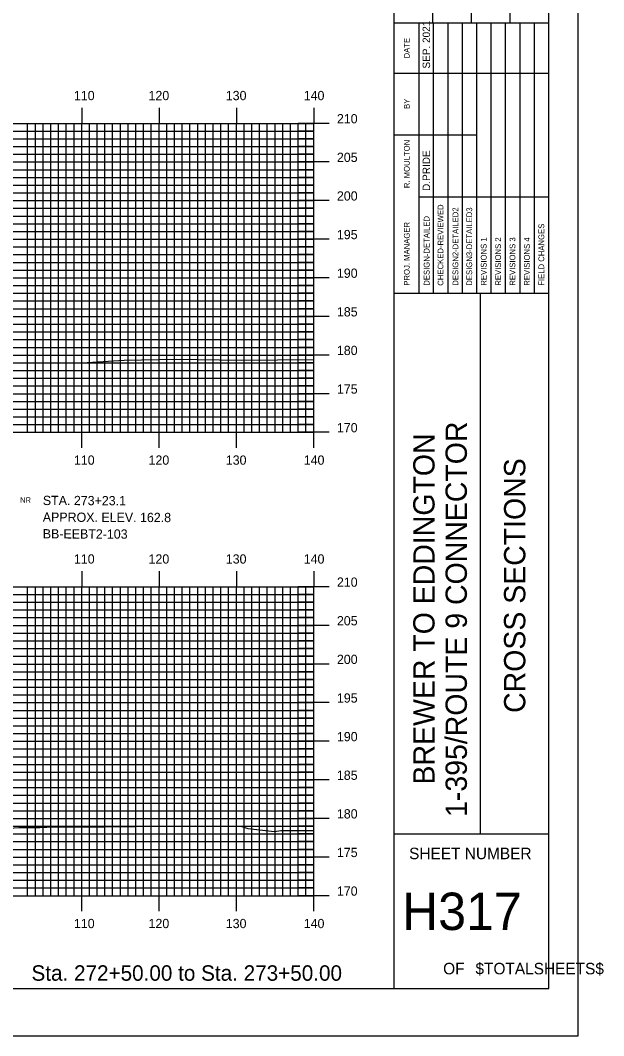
# Model space of a CAD drawing. Extents: x 1809013 to 1809356, y 442591 to 442811.
# Drawn here: x 1809280.4 to 1809355.8, y 442590.5 to 442722 of the extents above; entities that cross this region are included whole.
import ezdxf

# ---------------------------------------------------------------- set-up
doc = ezdxf.new("R2010")
doc.units = 0
for name, color, linetype in [('BORDER', 7, 'Continuous'), ('BORING - NO REFUSAL', 7, 'Continuous'), ('H_V ANNOTATION', 7, 'Continuous'), ('MAJOR', 7, 'Continuous'), ('MINOR', 7, 'Continuous'), ('PLOT BOUNDARY', 7, 'Continuous'), ('S_Roadway_Centerline', 7, 'Continuous')]:
    doc.layers.add(name, color=color, linetype=linetype)

msp = doc.modelspace()

# ---------------------------------------------------------------- linework, layer by layer
at = {"layer": 'BORDER'}
for p, q in [((1809328.72, 442596.67), (1809328.72, 442806.67)), ((1809333.72, 442721.67), (1809333.72, 442738.97)), ((1809338.72, 442721.67), (1809338.72, 442738.97)), ((1809343.72, 442721.67), (1809343.72, 442738.97)), ((1809328.72, 442721.67), (1809348.72, 442721.67)), ((1809328.72, 442686.67), (1809348.72, 442686.67)), ((1809339.91, 442616.67), (1809339.91, 442686.67)), ((1809328.72, 442616.67), (1809348.72, 442616.67))]:
    msp.add_line(p, q, dxfattribs=at)
msp.add_lwpolyline([(1809028.72, 442596.67), (1809348.72, 442596.67), (1809348.72, 442806.67), (1809028.72, 442806.67)], close=True, dxfattribs=at)
for points in [[(1809331.95, 442715.17), (1809331.95, 442721.67)], [(1809333.82, 442686.68), (1809333.82, 442721.67)], [(1809335.68, 442721.67), (1809335.68, 442686.68)], [(1809337.55, 442686.68), (1809337.55, 442721.67)], [(1809339.41, 442686.68), (1809339.41, 442721.67)], [(1809341.27, 442686.68), (1809341.27, 442721.67)], [(1809343.14, 442686.68), (1809343.14, 442721.67)], [(1809345, 442686.68), (1809345, 442721.67)], [(1809346.86, 442686.68), (1809346.86, 442721.67)], [(1809331.96, 442686.68), (1809331.96, 442720.26)], [(1809328.72, 442715.17), (1809348.72, 442715.17)], [(1809328.72, 442707.17), (1809331.96, 442707.17)], [(1809331.95, 442707.17), (1809339.41, 442707.17)], [(1809331.95, 442699.17), (1809348.72, 442699.17)]]:
    msp.add_lwpolyline(points, dxfattribs=at)
at = {"layer": 'MAJOR'}
for p, q in [((1809288.32, 442710.67), (1809288.32, 442708.67)), ((1809298.32, 442710.67), (1809298.32, 442708.67)), ((1809308.32, 442710.67), (1809308.32, 442708.67)), ((1809318.32, 442710.67), (1809318.32, 442708.67)), ((1809038.32, 442708.67), (1809318.32, 442708.67)), ((1809038.32, 442708.67), (1809318.32, 442708.67)), ((1809288.32, 442668.67), (1809288.32, 442708.67)), ((1809298.32, 442668.67), (1809298.32, 442708.67)), ((1809308.32, 442668.67), (1809308.32, 442708.67)), ((1809320.33, 442708.67), (1809316.32, 442708.67)), ((1809318.32, 442668.67), (1809318.32, 442708.67)), ((1809318.32, 442668.67), (1809318.32, 442708.67)), ((1809038.32, 442703.67), (1809318.32, 442703.67)), ((1809320.33, 442703.67), (1809316.32, 442703.67)), ((1809038.32, 442698.67), (1809318.32, 442698.67)), ((1809320.33, 442698.67), (1809316.32, 442698.67)), ((1809038.32, 442693.67), (1809318.32, 442693.67)), ((1809320.33, 442693.67), (1809316.32, 442693.67)), ((1809038.32, 442688.67), (1809318.32, 442688.67)), ((1809320.33, 442688.67), (1809316.32, 442688.67)), ((1809038.32, 442683.67), (1809318.32, 442683.67)), ((1809320.33, 442683.67), (1809316.32, 442683.67)), ((1809038.32, 442678.67), (1809318.32, 442678.67)), ((1809320.33, 442678.67), (1809316.32, 442678.67)), ((1809038.32, 442673.67), (1809318.32, 442673.67)), ((1809320.33, 442673.67), (1809316.32, 442673.67)), ((1809038.32, 442668.67), (1809318.32, 442668.67)), ((1809038.32, 442668.67), (1809318.32, 442668.67)), ((1809288.32, 442666.66), (1809288.32, 442668.67)), ((1809298.32, 442666.66), (1809298.32, 442668.67)), ((1809308.32, 442666.66), (1809308.32, 442668.67)), ((1809320.33, 442668.67), (1809316.32, 442668.67)), ((1809318.32, 442666.66), (1809318.32, 442668.67)), ((1809288.32, 442650.67), (1809288.32, 442648.67)), ((1809298.32, 442650.67), (1809298.32, 442648.67)), ((1809308.32, 442650.67), (1809308.32, 442648.67)), ((1809318.32, 442650.67), (1809318.32, 442648.67)), ((1809038.32, 442648.67), (1809318.32, 442648.67)), ((1809038.32, 442648.67), (1809318.32, 442648.67)), ((1809288.32, 442608.67), (1809288.32, 442648.67)), ((1809298.32, 442608.67), (1809298.32, 442648.67)), ((1809308.32, 442608.67), (1809308.32, 442648.67)), ((1809320.33, 442648.67), (1809316.32, 442648.67)), ((1809318.32, 442608.67), (1809318.32, 442648.67)), ((1809318.32, 442608.67), (1809318.32, 442648.67)), ((1809038.32, 442643.67), (1809318.32, 442643.67)), ((1809320.33, 442643.67), (1809316.32, 442643.67)), ((1809038.32, 442638.67), (1809318.32, 442638.67)), ((1809320.33, 442638.67), (1809316.32, 442638.67)), ((1809038.32, 442633.67), (1809318.32, 442633.67)), ((1809320.33, 442633.67), (1809316.32, 442633.67)), ((1809038.32, 442628.67), (1809318.32, 442628.67)), ((1809320.33, 442628.67), (1809316.32, 442628.67)), ((1809038.32, 442623.67), (1809318.32, 442623.67)), ((1809320.33, 442623.67), (1809316.32, 442623.67)), ((1809038.32, 442618.67), (1809318.32, 442618.67)), ((1809320.33, 442618.67), (1809316.32, 442618.67)), ((1809038.32, 442613.67), (1809318.32, 442613.67)), ((1809320.33, 442613.67), (1809316.32, 442613.67)), ((1809038.32, 442608.67), (1809318.32, 442608.67)), ((1809038.32, 442608.67), (1809318.32, 442608.67)), ((1809288.32, 442606.66), (1809288.32, 442608.67)), ((1809298.32, 442606.66), (1809298.32, 442608.67)), ((1809308.32, 442606.66), (1809308.32, 442608.67)), ((1809320.33, 442608.67), (1809316.32, 442608.67)), ((1809318.32, 442606.66), (1809318.32, 442608.67))]:
    msp.add_line(p, q, dxfattribs=at)
at = {"layer": 'MINOR'}
for p, q in [((1809281.32, 442668.67), (1809281.32, 442708.67)), ((1809282.32, 442668.67), (1809282.32, 442708.67)), ((1809283.32, 442668.67), (1809283.32, 442708.67)), ((1809284.32, 442668.67), (1809284.32, 442708.67)), ((1809285.32, 442668.67), (1809285.32, 442708.67)), ((1809286.32, 442668.67), (1809286.32, 442708.67)), ((1809287.32, 442668.67), (1809287.32, 442708.67)), ((1809289.32, 442668.67), (1809289.32, 442708.67)), ((1809290.32, 442668.67), (1809290.32, 442708.67)), ((1809291.32, 442668.67), (1809291.32, 442708.67)), ((1809292.32, 442668.67), (1809292.32, 442708.67)), ((1809293.32, 442668.67), (1809293.32, 442708.67)), ((1809294.32, 442668.67), (1809294.32, 442708.67)), ((1809295.32, 442668.67), (1809295.32, 442708.67)), ((1809296.32, 442668.67), (1809296.32, 442708.67)), ((1809297.32, 442668.67), (1809297.32, 442708.67)), ((1809299.32, 442668.67), (1809299.32, 442708.67)), ((1809300.32, 442668.67), (1809300.32, 442708.67)), ((1809301.32, 442668.67), (1809301.32, 442708.67)), ((1809302.32, 442668.67), (1809302.32, 442708.67)), ((1809303.32, 442668.67), (1809303.32, 442708.67)), ((1809304.32, 442668.67), (1809304.32, 442708.67)), ((1809305.32, 442668.67), (1809305.32, 442708.67)), ((1809306.32, 442668.67), (1809306.32, 442708.67)), ((1809307.32, 442668.67), (1809307.32, 442708.67)), ((1809309.32, 442668.67), (1809309.32, 442708.67)), ((1809310.32, 442668.67), (1809310.32, 442708.67)), ((1809311.32, 442668.67), (1809311.32, 442708.67)), ((1809312.32, 442668.67), (1809312.32, 442708.67)), ((1809313.32, 442668.67), (1809313.32, 442708.67)), ((1809314.32, 442668.67), (1809314.32, 442708.67)), ((1809315.32, 442668.67), (1809315.32, 442708.67)), ((1809316.32, 442668.67), (1809316.32, 442708.67)), ((1809317.32, 442668.67), (1809317.32, 442708.67)), ((1809038.32, 442707.67), (1809318.32, 442707.67)), ((1809318.32, 442707.67), (1809316.32, 442707.67)), ((1809038.32, 442706.67), (1809318.32, 442706.67)), ((1809038.32, 442705.67), (1809318.32, 442705.67)), ((1809318.32, 442706.67), (1809316.32, 442706.67)), ((1809318.32, 442705.67), (1809316.32, 442705.67)), ((1809038.32, 442704.67), (1809318.32, 442704.67)), ((1809318.32, 442704.67), (1809316.32, 442704.67)), ((1809038.32, 442702.67), (1809318.32, 442702.67)), ((1809038.32, 442701.67), (1809318.32, 442701.67)), ((1809318.32, 442702.67), (1809316.32, 442702.67)), ((1809318.32, 442701.67), (1809316.32, 442701.67)), ((1809038.32, 442700.67), (1809318.32, 442700.67)), ((1809318.32, 442700.67), (1809316.32, 442700.67)), ((1809038.32, 442699.67), (1809318.32, 442699.67)), ((1809318.32, 442699.67), (1809316.32, 442699.67)), ((1809038.32, 442697.67), (1809318.32, 442697.67)), ((1809318.32, 442697.67), (1809316.32, 442697.67)), ((1809038.32, 442696.67), (1809318.32, 442696.67)), ((1809318.32, 442696.67), (1809316.32, 442696.67)), ((1809038.32, 442695.67), (1809318.32, 442695.67)), ((1809318.32, 442695.67), (1809316.32, 442695.67)), ((1809038.32, 442694.67), (1809318.32, 442694.67)), ((1809318.32, 442694.67), (1809316.32, 442694.67)), ((1809038.32, 442692.67), (1809318.32, 442692.67)), ((1809318.32, 442692.67), (1809316.32, 442692.67)), ((1809038.32, 442691.67), (1809318.32, 442691.67)), ((1809318.32, 442691.67), (1809316.32, 442691.67)), ((1809038.32, 442690.67), (1809318.32, 442690.67)), ((1809318.32, 442690.67), (1809316.32, 442690.67)), ((1809038.32, 442689.67), (1809318.32, 442689.67)), ((1809318.32, 442689.67), (1809316.32, 442689.67)), ((1809038.32, 442687.67), (1809318.32, 442687.67)), ((1809318.32, 442687.67), (1809316.32, 442687.67)), ((1809038.32, 442686.67), (1809318.32, 442686.67)), ((1809318.32, 442686.67), (1809316.32, 442686.67)), ((1809038.32, 442685.67), (1809318.32, 442685.67)), ((1809038.32, 442684.67), (1809318.32, 442684.67)), ((1809318.32, 442685.67), (1809316.32, 442685.67)), ((1809318.32, 442684.67), (1809316.32, 442684.67)), ((1809038.32, 442682.67), (1809318.32, 442682.67)), ((1809318.32, 442682.67), (1809316.32, 442682.67)), ((1809038.32, 442681.67), (1809318.32, 442681.67)), ((1809038.32, 442680.67), (1809318.32, 442680.67)), ((1809318.32, 442681.67), (1809316.32, 442681.67)), ((1809318.32, 442680.67), (1809316.32, 442680.67)), ((1809038.32, 442679.67), (1809318.32, 442679.67)), ((1809318.32, 442679.67), (1809316.32, 442679.67)), ((1809038.32, 442677.67), (1809318.32, 442677.67)), ((1809038.32, 442676.67), (1809318.32, 442676.67)), ((1809318.32, 442677.67), (1809316.32, 442677.67)), ((1809318.32, 442676.67), (1809316.32, 442676.67)), ((1809038.32, 442675.67), (1809318.32, 442675.67)), ((1809318.32, 442675.67), (1809316.32, 442675.67)), ((1809038.32, 442674.67), (1809318.32, 442674.67)), ((1809318.32, 442674.67), (1809316.32, 442674.67)), ((1809038.32, 442672.67), (1809318.32, 442672.67)), ((1809318.32, 442672.67), (1809316.32, 442672.67)), ((1809038.32, 442671.67), (1809318.32, 442671.67)), ((1809318.32, 442671.67), (1809316.32, 442671.67)), ((1809038.32, 442670.67), (1809318.32, 442670.67)), ((1809318.32, 442670.67), (1809316.32, 442670.67)), ((1809038.32, 442669.67), (1809318.32, 442669.67)), ((1809318.32, 442669.67), (1809316.32, 442669.67)), ((1809038.32, 442647.67), (1809318.32, 442647.67)), ((1809281.32, 442608.67), (1809281.32, 442648.67)), ((1809282.32, 442608.67), (1809282.32, 442648.67)), ((1809283.32, 442608.67), (1809283.32, 442648.67)), ((1809284.32, 442608.67), (1809284.32, 442648.67)), ((1809285.32, 442608.67), (1809285.32, 442648.67)), ((1809286.32, 442608.67), (1809286.32, 442648.67)), ((1809287.32, 442608.67), (1809287.32, 442648.67)), ((1809289.32, 442608.67), (1809289.32, 442648.67)), ((1809290.32, 442608.67), (1809290.32, 442648.67)), ((1809291.32, 442608.67), (1809291.32, 442648.67)), ((1809292.32, 442608.67), (1809292.32, 442648.67)), ((1809293.32, 442608.67), (1809293.32, 442648.67)), ((1809294.32, 442608.67), (1809294.32, 442648.67)), ((1809295.32, 442608.67), (1809295.32, 442648.67)), ((1809296.32, 442608.67), (1809296.32, 442648.67)), ((1809297.32, 442608.67), (1809297.32, 442648.67)), ((1809299.32, 442608.67), (1809299.32, 442648.67)), ((1809300.32, 442608.67), (1809300.32, 442648.67)), ((1809301.32, 442608.67), (1809301.32, 442648.67)), ((1809302.32, 442608.67), (1809302.32, 442648.67)), ((1809303.32, 442608.67), (1809303.32, 442648.67)), ((1809304.32, 442608.67), (1809304.32, 442648.67)), ((1809305.32, 442608.67), (1809305.32, 442648.67)), ((1809306.32, 442608.67), (1809306.32, 442648.67)), ((1809307.32, 442608.67), (1809307.32, 442648.67)), ((1809309.32, 442608.67), (1809309.32, 442648.67)), ((1809310.32, 442608.67), (1809310.32, 442648.67)), ((1809311.32, 442608.67), (1809311.32, 442648.67)), ((1809312.32, 442608.67), (1809312.32, 442648.67)), ((1809313.32, 442608.67), (1809313.32, 442648.67)), ((1809314.32, 442608.67), (1809314.32, 442648.67)), ((1809315.32, 442608.67), (1809315.32, 442648.67)), ((1809316.32, 442608.67), (1809316.32, 442648.67)), ((1809318.32, 442647.67), (1809316.32, 442647.67)), ((1809317.32, 442608.67), (1809317.32, 442648.67)), ((1809038.32, 442646.67), (1809318.32, 442646.67)), ((1809318.32, 442646.67), (1809316.32, 442646.67)), ((1809038.32, 442645.67), (1809318.32, 442645.67)), ((1809318.32, 442645.67), (1809316.32, 442645.67)), ((1809038.32, 442644.67), (1809318.32, 442644.67)), ((1809318.32, 442644.67), (1809316.32, 442644.67)), ((1809038.32, 442642.67), (1809318.32, 442642.67)), ((1809318.32, 442642.67), (1809316.32, 442642.67)), ((1809038.32, 442641.67), (1809318.32, 442641.67)), ((1809318.32, 442641.67), (1809316.32, 442641.67)), ((1809038.32, 442640.67), (1809318.32, 442640.67)), ((1809318.32, 442640.67), (1809316.32, 442640.67)), ((1809038.32, 442639.67), (1809318.32, 442639.67)), ((1809318.32, 442639.67), (1809316.32, 442639.67)), ((1809038.32, 442637.67), (1809318.32, 442637.67)), ((1809318.32, 442637.67), (1809316.32, 442637.67)), ((1809038.32, 442636.67), (1809318.32, 442636.67)), ((1809318.32, 442636.67), (1809316.32, 442636.67)), ((1809038.32, 442635.67), (1809318.32, 442635.67)), ((1809038.32, 442634.67), (1809318.32, 442634.67)), ((1809318.32, 442635.67), (1809316.32, 442635.67)), ((1809318.32, 442634.67), (1809316.32, 442634.67)), ((1809038.32, 442632.67), (1809318.32, 442632.67)), ((1809318.32, 442632.67), (1809316.32, 442632.67)), ((1809038.32, 442631.67), (1809318.32, 442631.67)), ((1809038.32, 442630.67), (1809318.32, 442630.67)), ((1809318.32, 442631.67), (1809316.32, 442631.67)), ((1809318.32, 442630.67), (1809316.32, 442630.67)), ((1809038.32, 442629.67), (1809318.32, 442629.67)), ((1809318.32, 442629.67), (1809316.32, 442629.67)), ((1809038.32, 442627.67), (1809318.32, 442627.67)), ((1809038.32, 442626.67), (1809318.32, 442626.67)), ((1809318.32, 442627.67), (1809316.32, 442627.67)), ((1809318.32, 442626.67), (1809316.32, 442626.67)), ((1809038.32, 442625.67), (1809318.32, 442625.67)), ((1809318.32, 442625.67), (1809316.32, 442625.67)), ((1809038.32, 442624.67), (1809318.32, 442624.67)), ((1809318.32, 442624.67), (1809316.32, 442624.67)), ((1809038.32, 442622.67), (1809318.32, 442622.67)), ((1809318.32, 442622.67), (1809316.32, 442622.67)), ((1809038.32, 442621.67), (1809318.32, 442621.67)), ((1809318.32, 442621.67), (1809316.32, 442621.67)), ((1809038.32, 442620.67), (1809318.32, 442620.67)), ((1809318.32, 442620.67), (1809316.32, 442620.67)), ((1809038.32, 442619.67), (1809318.32, 442619.67)), ((1809318.32, 442619.67), (1809316.32, 442619.67)), ((1809038.32, 442617.67), (1809318.32, 442617.67)), ((1809318.32, 442617.67), (1809316.32, 442617.67)), ((1809038.32, 442616.67), (1809318.32, 442616.67)), ((1809318.32, 442616.67), (1809316.32, 442616.67)), ((1809038.32, 442615.67), (1809318.32, 442615.67)), ((1809318.32, 442615.67), (1809316.32, 442615.67)), ((1809038.32, 442614.67), (1809318.32, 442614.67)), ((1809318.32, 442614.67), (1809316.32, 442614.67)), ((1809038.32, 442612.67), (1809318.32, 442612.67)), ((1809318.32, 442612.67), (1809316.32, 442612.67)), ((1809038.32, 442611.67), (1809318.32, 442611.67)), ((1809318.32, 442611.67), (1809316.32, 442611.67)), ((1809038.32, 442610.67), (1809318.32, 442610.67)), ((1809038.32, 442609.67), (1809318.32, 442609.67)), ((1809318.32, 442610.67), (1809316.32, 442610.67)), ((1809318.32, 442609.67), (1809316.32, 442609.67))]:
    msp.add_line(p, q, dxfattribs=at)
at = {"layer": 'PLOT BOUNDARY'}
msp.add_lwpolyline([(1809012.54, 442590.55), (1809352.54, 442590.55), (1809352.54, 442810.55), (1809012.54, 442810.55)], close=True, dxfattribs=at)
at = {"layer": 'S_Roadway_Centerline'}
for points in [[(1809205.65, 442676.78), (1809207.67, 442676.78), (1809219.35, 442676.83), (1809222.57, 442676.83), (1809231.48, 442676.89), (1809234.9, 442676.9), (1809252.73, 442676.93), (1809252.96, 442676.93), (1809253.24, 442676.93), (1809256.39, 442676.94), (1809260.9, 442677.36), (1809265.23, 442677.45), (1809274.04, 442677.45), (1809276.16, 442677.27), (1809279.43, 442677.68), (1809289.04, 442677.69), (1809293.8, 442677.99), (1809300.57, 442678.12), (1809308.92, 442678), (1809318.32, 442678.09)], [(1809193.97, 442619.02), (1809218.3, 442618.76), (1809228.11, 442618.77), (1809236.02, 442618.69), (1809243.32, 442618.31), (1809251.38, 442617.73), (1809264.7, 442617.5), (1809274.69, 442617.17), (1809275.36, 442617.17), (1809276.46, 442617.23), (1809280.18, 442617.49), (1809282.88, 442617.51), (1809283.8, 442617.55), (1809291.27, 442617.59), (1809303.06, 442617.71), (1809308.91, 442617.68), (1809309.81, 442617.36), (1809313.26, 442616.98), (1809314.08, 442617.1), (1809318.32, 442617.11)]]:
    msp.add_lwpolyline(points, dxfattribs=at)

# ---------------------------------------------------------------- texts
at = {"layer": 'BORDER'}
for s, height, p in [('SEP. 2021', 0.969, (1809333.37, 442715.76)), ('DATE', 0.743, (1809330.73, 442717.08)), ('BY', 0.743, (1809330.73, 442710.54)), ('R. MOULTON', 0.745, (1809330.73, 442700.28)), ('D.PRIDE', 0.969, (1809333.37, 442699.92)), ('CHECKED-REVIEWED', 0.7455, (1809335.09, 442687.65)), ('DESIGN2-DETAILED2', 0.7455, (1809337.02, 442687.65)), ('DESIGN3-DETAILED3', 0.7455, (1809338.81, 442687.65)), ('DESIGN-DETAILED', 0.7455, (1809333.3, 442687.65)), ('PROJ. MANAGER', 0.7455, (1809330.73, 442687.65)), ('FIELD CHANGES', 0.7455, (1809348.13, 442687.65)), ('REVISIONS 1', 0.7455, (1809340.68, 442687.65)), ('REVISIONS 2', 0.7455, (1809342.54, 442687.65)), ('REVISIONS 3', 0.7455, (1809344.4, 442687.65)), ('REVISIONS 4', 0.7455, (1809346.27, 442687.65)), ('1-395/ROUTE 9 CONNECTOR', 2.7557, (1809338.13, 442618.87)), ('BREWER TO EDDINGTON', 2.7557, (1809333.95, 442623.07)), ('CROSS SECTIONS', 2.7557, (1809345.69, 442632.34))]:
    msp.add_text(s, height=height, rotation=90, dxfattribs=at).set_placement(p)
for s, height, p in [('SHEET NUMBER', 1.4905, (1809330.66, 442613.4)), ('H317', 4.839, (1809329.75, 442604.23)), ('OF', 1.491, (1809335.06, 442598.49)), ('$TOTALSHEETS$', 1.4905, (1809339.24, 442598.49))]:
    msp.add_text(s, height=height, dxfattribs=at).set_placement(p)
at = {"layer": 'BORING - NO REFUSAL'}
msp.add_text('NR', height=0.7, dxfattribs=at).set_placement((1809280.36, 442659.55))
for s, p in [('STA. 273+23.1', (1809283.29, 442659.25)), ('APPROX. ELEV. 162.8', (1809283.28, 442657.09)), ('BB-EEBT2-103', (1809283.28, 442654.93))]:
    msp.add_text(s, height=1.2, rotation=359.8142, dxfattribs=at).set_placement(p)
at = {"layer": 'H_V ANNOTATION'}
for s, height, p in [('110', 1.2, (1809287.31, 442711.67)), ('120', 1.2, (1809296.96, 442711.67)), ('130', 1.2, (1809306.95, 442711.67)), ('140', 1.2, (1809317.03, 442711.67)), ('210', 1.2, (1809321.32, 442708.67)), ('205', 1.2, (1809321.32, 442703.67)), ('200', 1.2, (1809321.32, 442698.67)), ('195', 1.2, (1809321.32, 442693.67)), ('190', 1.2, (1809321.32, 442688.67)), ('185', 1.2, (1809321.32, 442683.67)), ('180', 1.2, (1809321.32, 442678.67)), ('175', 1.2, (1809321.32, 442673.67)), ('170', 1.2, (1809321.32, 442668.67)), ('110', 1.2, (1809287.31, 442664.47)), ('120', 1.2, (1809296.96, 442664.47)), ('130', 1.2, (1809306.95, 442664.47)), ('140', 1.2, (1809317.03, 442664.47)), ('110', 1.2, (1809287.31, 442651.67)), ('120', 1.2, (1809296.96, 442651.67)), ('130', 1.2, (1809306.95, 442651.67)), ('140', 1.2, (1809317.03, 442651.67)), ('210', 1.2, (1809321.32, 442648.67)), ('205', 1.2, (1809321.32, 442643.67)), ('200', 1.2, (1809321.32, 442638.67)), ('195', 1.2, (1809321.32, 442633.67)), ('190', 1.2, (1809321.32, 442628.67)), ('185', 1.2, (1809321.32, 442623.67)), ('180', 1.2, (1809321.32, 442618.67)), ('175', 1.2, (1809321.32, 442613.67)), ('170', 1.2, (1809321.32, 442608.67)), ('110', 1.2, (1809287.31, 442604.47)), ('120', 1.2, (1809296.96, 442604.47)), ('130', 1.2, (1809306.95, 442604.47)), ('140', 1.2, (1809317.03, 442604.47)), ('Sta. 272+50.00 to Sta. 273+50.00', 2.0004, (1809281.82, 442597.66))]:
    msp.add_text(s, height=height, dxfattribs=at).set_placement(p)

doc.saveas('drawing.dxf')
